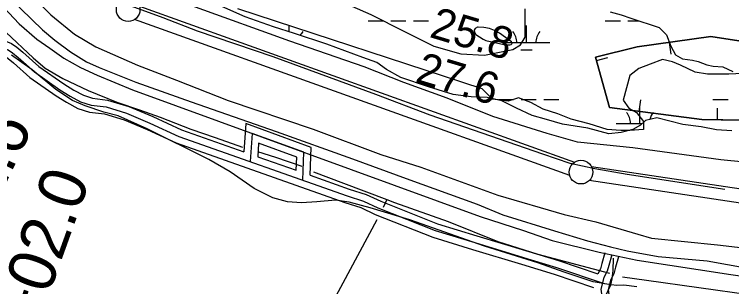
# Model space of a CAD drawing. Extents: x 3297772 to 3335630, y 634068 to 659439.
# Drawn here: x 3320374 to 3321893, y 644849 to 645425 of the extents above; entities that cross this region are included whole.
import ezdxf

# ---------------------------------------------------------------- set-up
doc = ezdxf.new("R2010")
doc.units = 0
for name, color, linetype in [('V-BORW-LINE', 7, 'Continuous'), ('V-DTCH-CNTR', 7, 'Continuous'), ('V-FLOD-BASE', 7, 'Continuous'), ('V-LEVE-TOET', 7, 'Continuous'), ('V-RIVR-EDGE', 7, 'Continuous'), ('V-RIVR-RANG', 7, 'Continuous'), ('V-ROAD-CNTR', 7, 'Continuous'), ('V-SITE-VEGE', 7, 'Continuous'), ('V-SURV-IDEN', 7, 'Continuous'), ('V-SURV-LINE', 7, 'Continuous'), ('V-TOPO-MAJR', 7, 'Continuous'), ('V-TOPO-SHOR', 7, 'Continuous'), ('V-WETL-SWMP', 7, 'Continuous')]:
    doc.layers.add(name, color=color, linetype=linetype)

msp = doc.modelspace()

# ---------------------------------------------------------------- linework, layer by layer
at = {"layer": 'V-BORW-LINE'}
for p, q in [((3321760.2, 645365.8), (3321763.7, 645341)), ((3321606.6, 645327.3), (3321630.7, 645334)), ((3321697, 645219.7), (3321700.2, 645244.4)), ((3321862.5, 645202), (3321862.9, 645227))]:
    msp.add_line(p, q, dxfattribs=at)
for points in [[(3322142.3, 645197.5), (3321829.2, 645202.5), (3321634.3, 645227.8), (3321604.5, 645334.7), (3321692.8, 645356.4), (3321848.6, 645378.2), (3322013.1, 645352.8), (3322176.6, 645319.6), (3322203.6, 645239.1), (3322140.5, 645197.5)], [(3322099.6, 645335.2), (3322013.1, 645352.8), (3321848.6, 645378.2), (3321692.8, 645356.4), (3321604.5, 645334.7), (3321634.3, 645227.8), (3321829.2, 645202.5), (3322076, 645198.6)]]:
    msp.add_lwpolyline(points, dxfattribs=at)
at = {"layer": 'V-DTCH-CNTR'}
for points in [[(3321691.8, 644848.5), (3321664.3, 644852.2), (3321649.5, 644851.3), (3321637.7, 644852.8), (3321637, 644852.9), (3321599.3, 644859.6), (3321538.1, 644879.5), (3321482.4, 644899.5), (3321369.5, 644934.7), (3321211, 644990.7), (3321127.1, 645015.9), (3321083.1, 645028.1), (3321054.2, 645031.8), (3321014.3, 645028.4), (3320982.2, 645026.6), (3320952.4, 645028.8), (3320921.1, 645037.2), (3320881.8, 645056.5), (3320830.7, 645092.1), (3320785.9, 645118.4), (3320655.5, 645183.2), (3320594.2, 645210.2), (3320563.7, 645218.6), (3320523.7, 645231.6), (3320497, 645243.1), (3320461.6, 645266.4), (3320412, 645307.5), (3320367.9, 645338.5)], [(3321637, 644852.9), (3321640, 644865.5), (3321641.5, 644883.5), (3321642.3, 644909.4)], [(3321333.3, 644215.8), (3321358.2, 644271.6), (3321398.8, 644362.6), (3321516.1, 644600.6), (3321576.3, 644723.9), (3321637, 644852.9)]]:
    msp.add_lwpolyline(points, dxfattribs=at)
at = {"layer": 'V-FLOD-BASE'}
msp.add_lwpolyline([(3321878.2, 645054.7), (3321671.6, 645086.4), (3321602.8, 645098.5), (3321550.5, 645110), (3321492.7, 645129.3), (3321254.4, 645212.2), (3321139.5, 645255.6), (3320921.7, 645335.4), (3320761.7, 645389.6), (3320688.8, 645417.5), (3320621.5, 645442.3), (3320580.3, 645461), (3320547.8, 645483.7), (3320508.8, 645515.8), (3320466.6, 645559.7), (3320403.7, 645639.9), (3320311.2, 645756.9)], dxfattribs=at)
at = {"layer": 'V-LEVE-TOET'}
for points in [[(3318948.8, 646161.3), (3319040.6, 646128), (3319139.6, 646094.7), (3319302.7, 646039.8), (3319440.5, 645992.5), (3319640.9, 645927.6), (3319819, 645868), (3320038.4, 645789), (3320082, 645767.2), (3320110.5, 645756.3), (3320147.8, 645745.5), (3320169.1, 645735.4), (3320186.6, 645723.7), (3320202.6, 645701.7), (3320224.9, 645675), (3320318.1, 645564.2), (3320410.4, 645465.3), (3320451, 645424.5), (3320501.1, 645383)], [(3322034.1, 645097.9), (3322012.9, 645103.5), (3321869.8, 645117.5), (3321683.2, 645143), (3321566.2, 645154.8), (3321502.1, 645173.3), (3321387.3, 645208.9), (3321290.6, 645247.7), (3321198.8, 645281), (3321114.8, 645314.4), (3320957.2, 645368.6), (3320757.6, 645440.6), (3320620.6, 645484.7), (3320584.1, 645505.8), (3320543.6, 645536.3), (3320505.4, 645582.6), (3320452, 645645.5), (3320390.6, 645731.9), (3320330, 645806.6)], [(3320501.1, 645383), (3320546.3, 645356.5), (3320635, 645317.6), (3320717.4, 645285.8), (3320826.7, 645243.1), (3321006.5, 645182), (3321149.9, 645128.5), (3321234.6, 645102.2), (3321397.8, 645042.6), (3321537.9, 645001.7), (3321605.1, 644986.3), (3321693.9, 644960.5)], [(3321693.9, 644960.5), (3321723.1, 644951.6), (3321863, 644937.6), (3321988.7, 644922.7), (3322195.2, 644888.6), (3322317.7, 644869.7), (3322494.9, 644842.5), (3322603.2, 644826.7), (3322878.5, 644784.4)]]:
    msp.add_lwpolyline(points, dxfattribs=at)
at = {"layer": 'V-RIVR-EDGE'}
msp.add_spline([(3321122.9, 645812.2), (3321138.4, 645807.6), (3321145.4, 645808.7), (3321149.8, 645810.5), (3321155.3, 645810.5), (3321158.9, 645809), (3321164.7, 645803.9), (3321170.6, 645800.9), (3321175.3, 645800.9), (3321179, 645800.9), (3321185.2, 645800.9), (3321214.4, 645789.5), (3321242.5, 645780.6), (3321282.7, 645770.7), (3321301, 645765.1), (3321304.3, 645767), (3321306.9, 645768.4), (3321313.4, 645768), (3321317.4, 645764), (3321319.3, 645761.8), (3321341.9, 645758.1), (3321355.1, 645756.2), (3321364.9, 645752.6), (3321386.9, 645746.3), (3321408, 645739.7), (3321426.7, 645734.1), (3321431.1, 645733.7), (3321446, 645730.8), (3321501.6, 645723.7), (3321519.8, 645719.6), (3321538.9, 645719.6), (3321562.6, 645714.8), (3321579.4, 645708.9), (3321585.6, 645702.7), (3321591.8, 645701.5), (3321625.1, 645693.8), (3321641.9, 645691.2), (3321653.9, 645689), (3321666.7, 645688.6), (3321679.5, 645688.2), (3321688.7, 645687.8), (3321698.9, 645686.3), (3321725.9, 645677.1), (3321747.1, 645672.3), (3321767.2, 645667.5), (3321793.1, 645657.6), (3321806.6, 645651.7), (3321827.5, 645645.4), (3321843.9, 645643.2), (3321857.4, 645639.1), (3321868, 645635.1), (3321887, 645631.4), (3321909.7, 645623.3), (3321931.2, 645618.8), (3321956.8, 645609.6), (3321991.8, 645598.9), (3322021.1, 645592.3), (3322042.3, 645586.4), (3322071.8, 645576.1), (3322089.7, 645568.7), (3322115.3, 645562.8), (3322126.3, 645561.3), (3322128.5, 645561.3), (3322128.5, 645563.5), (3322120.8, 645573.8), (3322119.4, 645578.5), (3322120.1, 645580.3), (3322121.9, 645580.7), (3322159.2, 645570.4), (3322191, 645559.7), (3322216.2, 645550.5), (3322238.1, 645543.5), (3322253.1, 645536.9), (3322274.6, 645531), (3322294.3, 645522.9), (3322303.1, 645518.1), (3322317, 645515.5), (3322329.8, 645511.5), (3322336.3, 645508.2), (3322351.7, 645502.6), (3322379.1, 645494.2), (3322394, 645492.7), (3322401.4, 645492.3), (3322413.8, 645483.5), (3322428.4, 645478.7), (3322445.2, 645476.1), (3322459.4, 645472.8), (3322468.6, 645470.5), (3322479.2, 645468), (3322500.7, 645466.4), (3322517.2, 645462.4), (3322539.1, 645458.3), (3322587.7, 645446.5), (3322615.4, 645438.4), (3322629.7, 645437.2), (3322656.7, 645432.1), (3322669.2, 645431.7), (3322686, 645432.7), (3322709, 645429.4), (3322741.5, 645426.7), (3322769.7, 645425.6), (3322792.3, 645423.3), (3322830, 645417), (3322876.4, 645413.2), (3322894.6, 645411.7), (3322925.7, 645410.6), (3322951.3, 645409), (3322968.5, 645406.8), (3322991.1, 645405.6), (3323001, 645405.6), (3323020, 645404.1), (3323041.6, 645401.5), (3323068.2, 645395.6), (3323083.2, 645392.6), (3323108.1, 645390.7), (3323127.8, 645390.3), (3323146.5, 645391.4), (3323158.5, 645391.7), (3323178.6, 645390.9), (3323186.7, 645387.3), (3323193.6, 645387.6), (3323214.4, 645386.8), (3323229.8, 645386.4), (3323236, 645388.6), (3323242.2, 645388.2), (3323247.3, 645384.9), (3323255, 645384.2), (3323280.2, 645381.5), (3323317.5, 645379.3), (3323350, 645376.6), (3323376, 645372.5), (3323403, 645370.6), (3323452.4, 645371.6), (3323484.2, 645373.4), (3323495.9, 645374.1), (3323503.2, 645376.2), (3323516.7, 645379.1), (3323532.1, 645379.8), (3323552.9, 645382), (3323562.4, 645381.9), (3323570.1, 645381.9), (3323578.1, 645381.2), (3323601.5, 645378.6), (3323618.7, 645378.5), (3323643.9, 645375.9), (3323672.1, 645375.5), (3323701, 645377.9), (3323726.5, 645375.7), (3323756.5, 645372.7), (3323766, 645373.4), (3323779.6, 645376.3), (3323798.2, 645378.1), (3323820.9, 645378), (3323843.9, 645377.6), (3323868.7, 645376.1), (3323894.3, 645374.5), (3323916.3, 645374.1), (3323941.9, 645375.5), (3323966.4, 645379.1), (3323979.5, 645379.8), (3323990.5, 645379.8), (3324002.2, 645376.5), (3324019.7, 645365.8), (3324029.2, 645363.6), (3324041.6, 645364.3), (3324055.9, 645368.3), (3324070.1, 645367.5), (3324089.5, 645365.3), (3324122.8, 645364.5), (3324137.4, 645363), (3324149.5, 645362.9), (3324171, 645363.3), (3324183.1, 645363.2), (3324194.4, 645360.6), (3324212.3, 645360.6), (3324227.3, 645361.3), (3324239.7, 645362.7), (3324254, 645362.3), (3324275.2, 645359.7), (3324284.7, 645360), (3324298.6, 645360.7), (3324315.8, 645361.4), (3324339.5, 645360.6), (3324360.7, 645361), (3324392.9, 645360.9), (3324417, 645359.4), (3324435.3, 645362.2), (3324454, 645360.4), (3324475.5, 645357.7), (3324498.9, 645357.3), (3324531.4, 645356.1), (3324558.5, 645357.2), (3324596.1, 645356.4), (3324618.4, 645355.2), (3324646.6, 645353.7), (3324666, 645355.8), (3324683.5, 645353.9), (3324697.7, 645350.6), (3324711.3, 645349.5), (3324734.7, 645348.3), (3324754, 645346.5), (3324777.1, 645345.3), (3324800.8, 645341.6), (3324818.4, 645343), (3324834.1, 645344.8), (3324855.3, 645346.9), (3324875.4, 645346.2), (3324888.9, 645343.2), (3324907.6, 645342.1), (3324921.8, 645341.7), (3324946.7, 645338.3), (3324963.1, 645338.6), (3324989.1, 645337.5), (3325010.6, 645335.2), (3325034.7, 645334.1), (3325053, 645333.7), (3325072.8, 645334.7), (3325094, 645337.9), (3325121.8, 645343.4), (3325141.5, 645350.6), (3325171.9, 645358.2), (3325196.8, 645366.6)], degree=3, dxfattribs=at)
at = {"layer": 'V-ROAD-CNTR'}
for points in [[(3320273.5, 645523.2), (3320384.6, 645404.9), (3320421.8, 645372.7), (3320449.2, 645353.9), (3320478.7, 645332.5), (3320514, 645313), (3320549.6, 645296.2), (3320624.2, 645265.5), (3321360.3, 644997.6), (3321451.7, 644967.7), (3321513, 644946.6), (3321612.1, 644922.1), (3321692.4, 644905.4), (3321891.1, 644874.7), (3322673.6, 644762.4)], [(3320307.5, 645340.2), (3320324.5, 645350.7), (3320338.7, 645355.2), (3320352.1, 645353.8), (3320360.8, 645350.1), (3320370.2, 645343.8), (3320382.1, 645334.1), (3320416.4, 645303.4), (3320470.7, 645265.3), (3320492.3, 645252.1), (3320514.3, 645240.1), (3320536.6, 645233.3), (3320568.2, 645229.2), (3320611.4, 645216), (3320661.2, 645195.1), (3320722.4, 645167.1), (3321078.5, 645041.3), (3321113.3, 645030.3), (3321143.9, 645015.9), (3321265.1, 644968), (3321348.7, 644942.3), (3321452, 644911), (3321521.6, 644889.9), (3321622.6, 644855.7)], [(3320343.6, 645369.8), (3320355.8, 645368.5), (3320368, 645363.4), (3320379.1, 645355.9), (3320391.8, 645345.5), (3320425.7, 645315.1), (3320478.9, 645277.9), (3320499.8, 645265.1), (3320520.2, 645254), (3320539.8, 645248), (3320571.4, 645243.9), (3320616.5, 645230.1), (3320667.2, 645208.8), (3320728.1, 645181), (3320859.9, 645134.5)], [(3320318.3, 645329.2), (3320330.8, 645337), (3320340.3, 645340), (3320348.3, 645339.1), (3320353.7, 645336.9), (3320361.3, 645331.8), (3320372.3, 645322.7), (3320407, 645291.6), (3320462.4, 645252.8), (3320484.8, 645239.1), (3320508.5, 645226.2), (3320533.4, 645218.6), (3320565, 645214.5), (3320606.3, 645201.9), (3320655.1, 645181.3), (3320716.8, 645153.2), (3321073.7, 645027.1), (3321107.9, 645016.3), (3321137.9, 645002.1), (3321260.2, 644953.8), (3321344.3, 644927.9), (3321447.7, 644896.6), (3321517, 644875.6), (3321600, 644847.5)], [(3321000.2, 645084.9), (3321002.7, 645143.7), (3320863.8, 645194.3), (3320859.9, 645134.5)], [(3320984.7, 645074.5), (3320987.2, 645133.4), (3320877.5, 645173.3), (3320873.6, 645113.7)], [(3320970.6, 645095.4), (3320971.8, 645123), (3320891.1, 645152.4), (3320889.3, 645124.1)], [(3320889.3, 645124.1), (3320970.6, 645095.4)], [(3321000.2, 645084.9), (3321083.2, 645055.6), (3321118.8, 645044.3), (3321149.8, 645029.7), (3321270.1, 644982.2), (3321353.1, 644956.6), (3321456.4, 644925.3), (3321526.2, 644904.2), (3321609.1, 644876.1)], [(3321638.8, 644916.6), (3321632.4, 644894.1), (3321629.2, 644881.6), (3321622.2, 644868.7), (3321615.6, 644844), (3321617, 644833.6), (3321613.2, 644818.7), (3321604, 644797), (3321546.1, 644686.7), (3321490.6, 644559.3), (3321399.3, 644372.6), (3321338.1, 644239.4), (3321214.6, 643976.7), (3321091.1, 643716.1), (3321017.4, 643556.6), (3321000.3, 643517.5), (3320979.4, 643460.6), (3320961.8, 643424.4), (3320775.8, 643036.1), (3320642.2, 642753.4)], [(3321624.4, 644920.7), (3321617.9, 644898), (3321615.1, 644887.1), (3321609.1, 644876.1)], [(3321653.2, 644912.4), (3321646.9, 644890.2), (3321643.2, 644876.1), (3321636.2, 644863.1), (3321630.9, 644843), (3321632.3, 644832.7), (3321627.5, 644813.9), (3321617.6, 644790.5), (3321559.6, 644680.2), (3321504.2, 644553), (3321412.8, 644366.2), (3321374.8, 644283.3)]]:
    msp.add_lwpolyline(points, dxfattribs=at)
at = {"layer": 'V-SITE-VEGE'}
for points in [[(3321059.6, 645455.9), (3321128.8, 645424.9), (3321200.3, 645389.1), (3321262.3, 645358.1), (3321319.5, 645341.4), (3321369.5, 645339), (3321429.1, 645350.9), (3321445.8, 645360.5), (3321455.4, 645377.2), (3321455.4, 645410.6), (3321455.4, 645436.8)], [(3321932.2, 645300.8), (3321886.9, 645298.5), (3321841.6, 645298.5), (3321815.3, 645303.2), (3321784.4, 645317.5), (3321767.7, 645324.7), (3321746.2, 645329.5), (3321720, 645319.9), (3321696.1, 645310.4), (3321677.1, 645296.1), (3321662.8, 645243.6), (3321674.7, 645226.9), (3321691.4, 645217.4), (3321705.7, 645198.3), (3321705.7, 645181.6), (3321677.1, 645179.2), (3321658, 645179.2), (3321629.4, 645181.6), (3321591.2, 645193.5), (3321553.1, 645203.1), (3321524.5, 645215), (3321493.5, 645224.5), (3321467.3, 645238.8), (3321441.1, 645248.4), (3321419.6, 645241.2), (3321386.2, 645246), (3321364.8, 645267.5), (3320847.5, 645436.8)]]:
    msp.add_lwpolyline(points, dxfattribs=at)
at = {"layer": 'V-SURV-LINE'}
for points in [[(3320638.8, 645442.4), (3321560, 645112.3)], [(3321549.9, 645084), (3320628.7, 645414.2)], [(3321595.7, 645103.3), (3322924.5, 644904.9)], [(3322920.1, 644875.2), (3321591.3, 645073.6)]]:
    msp.add_lwpolyline(points, dxfattribs=at)
for centre in [(3320615, 645435), (3321573.7, 645091.4)]:
    msp.add_circle(centre, 25, dxfattribs=at)
at = {"layer": 'V-TOPO-MAJR'}
msp.add_lwpolyline([(3321427.7, 645363.9), (3321427.4, 645365.2), (3321426.5, 645366.7), (3321401.1, 645385.1), (3321390.7, 645391.1), (3321379.8, 645395.5), (3321368.2, 645397.6), (3321356.1, 645398), (3321354.7, 645397.9), (3321349.9, 645395.1), (3321347.3, 645391.8), (3321348, 645387.6), (3321350.8, 645382.9), (3321366.4, 645373), (3321369.3, 645371.4), (3321372.3, 645370.1), (3321375.3, 645369), (3321378.5, 645368.2), (3321414.2, 645361), (3321417.1, 645360.7), (3321420, 645360.6), (3321422.8, 645360.9), (3321425.7, 645361.6), (3321427, 645362.7), (3321427.7, 645363.9)], dxfattribs=at)
at = {"layer": 'V-TOPO-SHOR'}
msp.add_line((3321162.7, 645033.3), (3321154.9, 645016.6), dxfattribs=at)
for points in [[(3320206, 645633.6), (3320267.5, 645568.2), (3320388, 645436.8), (3320433.5, 645392.7), (3320459.8, 645370.7), (3320493.3, 645345.6), (3320526.7, 645324.4), (3320553.7, 645312.7), (3320631.6, 645281.6), (3320748.4, 645240.4), (3320928.7, 645177.5), (3321089.9, 645119.2), (3321203.5, 645078), (3321353.7, 645023.6), (3321408.5, 645001), (3321517.3, 644966.9), (3321587.2, 644946), (3321636.4, 644933.7), (3321671.3, 644925.2), (3321737.2, 644913), (3321841, 644903.5), (3321926.7, 644888.2), (3322063.9, 644870.2), (3322259.1, 644841.4)], [(3320357.1, 645386.6), (3320413.7, 645333.1), (3320439.3, 645311.1), (3320476.7, 645289.2), (3320530.7, 645264.2), (3320591.1, 645239.3), (3320638.8, 645223), (3320682.5, 645207.5), (3320747.6, 645182.6), (3320799.2, 645164.7), (3320857.2, 645144.5)], [(3320889, 645135.2), (3320927.1, 645122.8), (3320982.7, 645104.2)], [(3321007.3, 645091.7), (3321070.9, 645068.4), (3321162.7, 645033.3), (3321179, 645027.1), (3321292.5, 644986.7), (3321397.4, 644944.7), (3321482.4, 644917.6), (3321634, 644877.4)], [(3321141.2, 644990.4), (3321028.6, 644780.4), (3320892.5, 644517.2), (3320862.9, 644454.4)], [(3321661.8, 644869.7), (3321712.6, 644862.9), (3321933.9, 644832), (3322146.4, 644801), (3322360.6, 644770), (3322420.9, 644760.2), (3322634.2, 644730), (3322814.3, 644703.5), (3322867.4, 644700.7), (3322950.6, 644697.3), (3323134.5, 644690.7), (3323206.6, 644689.6)]]:
    msp.add_lwpolyline(points, dxfattribs=at)
at = {"layer": 'V-WETL-SWMP'}
for p, q in [((3320956.1, 645388.4), (3320956.1, 645401.3)), ((3321123.1, 645411.7), (3321155.1, 645411.7)), ((3321171.1, 645411.7), (3321203.1, 645411.7)), ((3321219.1, 645411.7), (3321251.1, 645411.7)), ((3321458, 645365.3), (3321458, 645401.3)), ((3321625, 645411.7), (3321657, 645411.7)), ((3321673, 645411.7), (3321696, 645411.7)), ((3321408, 645365.3), (3321508, 645365.3)), ((3321446, 645349.8), (3321470, 645349.8)), ((3321399.1, 645245.2), (3321431.1, 645245.2)), ((3321447.1, 645245.2), (3321479.1, 645245.2)), ((3321495.1, 645245.2), (3321527.1, 645245.2)), ((3321853, 645245.2), (3321885, 645245.2)), ((3321698.5, 645194.4), (3321698.5, 645230.4)), ((3321648.5, 645194.4), (3321703.4, 645194.4))]:
    msp.add_line(p, q, dxfattribs=at)
for points in [[(3321892.7, 645178.8), (3321860.7, 645181), (3321828, 645187), (3321789, 645192.1), (3321734.4, 645206.5), (3321710.3, 645200.9), (3321699.4, 645190.7), (3321683.1, 645181.3), (3321659, 645174.9), (3321632.6, 645172.3), (3321588.1, 645184.5), (3321534.3, 645192.7), (3321500.7, 645202.6), (3321470.3, 645210.9), (3321437.4, 645227), (3321406.2, 645242.4), (3321375, 645249.2), (3321341.5, 645250.5), (3321303.2, 645255.7), (3321250.9, 645271.7), (3321192.4, 645291.5), (3321161.9, 645308.4), (3321141.5, 645323.1), (3321111.9, 645333.8), (3321035.3, 645362.1), (3320967.4, 645385), (3320922.9, 645398.7), (3320862.8, 645420.1), (3320770.5, 645461.5)], [(3321635.4, 645430.2), (3321658.8, 645424.1), (3321679.1, 645417.3), (3321739.2, 645397.4), (3321754.9, 645382), (3321763.7, 645357.9), (3321773.9, 645339.2), (3321788.8, 645330.8), (3321809.8, 645328.6), (3321821.5, 645325.6), (3321840.3, 645318.7), (3321853.6, 645315.7), (3321873.8, 645314.2), (3321894.9, 645304.3)]]:
    msp.add_lwpolyline(points, dxfattribs=at)
for centre, start, end in [((3321011.3, 645365.7), 139.2282, 154.5498), ((3321402.7, 645365.7), 359.2282, 40.7718), ((3321513.2, 645365.7), 139.2282, 180.7718), ((3321643.2, 645194.9), 359.2282, 40.7718), ((3321753.7, 645194.9), 139.2282, 166.6644)]:
    msp.add_arc(centre, 35.2, start, end, dxfattribs=at)

# ---------------------------------------------------------------- texts
at = {"layer": 'V-RIVR-RANG'}
for s, p in [('25.8', (3321250.6, 645377.7)), ('27.6', (3321220.4, 645282.4))]:
    msp.add_text(s, height=67, rotation=343.3683, dxfattribs=at).set_placement(p)
at = {"layer": 'V-SURV-IDEN'}
for s, rotation, p in [('4600+61.6', 64.3244, (3320138.6, 644614)), ('4602+02.0', 70.2197, (3320320, 644477.4))]:
    msp.add_text(s, height=100, rotation=rotation, dxfattribs=at).set_placement(p)

doc.saveas('drawing.dxf')
